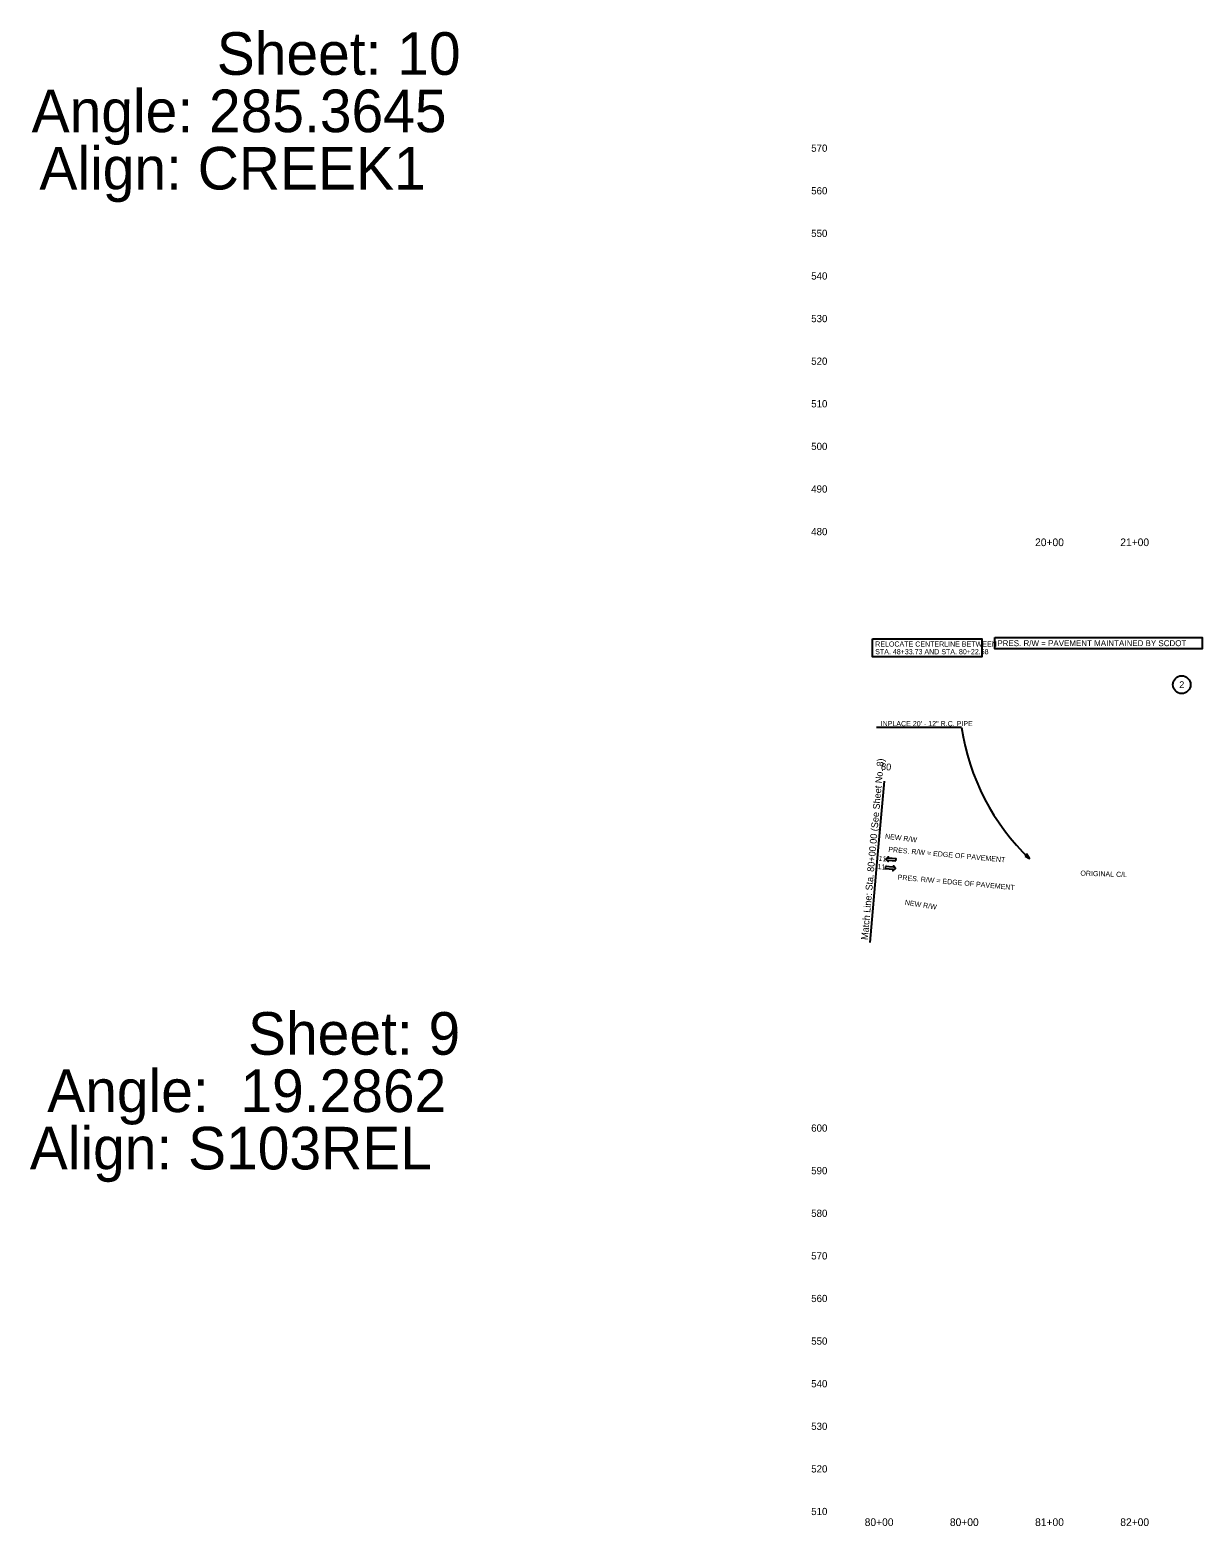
# Model space of a CAD drawing. Extents: x 1964377 to 1966966, y 1116414 to 1123213.
# Drawn here: x 1964377 to 1965753, y 1119864 to 1121620 of the extents above; entities that cross this region are included whole.
import ezdxf

# ---------------------------------------------------------------- set-up
doc = ezdxf.new("R2010")
doc.units = 0
for name, color, linetype in [('RD_DDB_Profile_Elev', 7, 'Continuous'), ('RD_DDB_StaTX', 7, 'Continuous'), ('RD_EX_DV_TX_Prop', 7, 'Continuous'), ('RD_EX_RW_TX', 7, 'Continuous'), ('RD_HC_Data_Rel', 7, 'Continuous'), ('RD_HC_TX_Rel_Sta50', 7, 'Continuous'), ('RD_PD_Final_LnLine', 7, 'Continuous'), ('RD_PD_Final_TX', 7, 'Continuous'), ('RD_PD_RW_TX', 7, 'Continuous'), ('RD_SHT_MatchLine', 7, 'Continuous'), ('RD_SHT_TX', 7, 'Continuous'), ('RD_TX_Drainage', 7, 'Continuous'), ('RD_TX_RoadID', 7, 'Continuous')]:
    doc.layers.add(name, color=color, linetype=linetype)

msp = doc.modelspace()

# ---------------------------------------------------------------- linework, layer by layer
at = {"layer": 'RD_EX_DV_TX_Prop'}
msp.add_circle((1965728.7, 1120851.4), 10.4, dxfattribs=at)
at = {"layer": 'RD_EX_RW_TX'}
msp.add_lwpolyline([(1965509.3, 1120906.6), (1965752.6, 1120906.6), (1965752.6, 1120893.6), (1965509.3, 1120893.6)], close=True, dxfattribs=at)
at = {"layer": 'RD_HC_Data_Rel'}
msp.add_lwpolyline([(1965365.9, 1120905.1), (1965494.2, 1120905.1), (1965494.2, 1120884.1), (1965365.9, 1120884.1)], close=True, dxfattribs=at)
at = {"layer": 'RD_PD_Final_LnLine'}
for points in [[(1965393.3, 1120644.5), (1965393.5, 1120646.9), (1965384.3, 1120647.7), (1965384.5, 1120649.3), (1965381.4, 1120646.8), (1965384, 1120643.7), (1965384.1, 1120645.3)], [(1965381, 1120638), (1965380.7, 1120635.6), (1965389.9, 1120634.8), (1965389.7, 1120633.1), (1965392.8, 1120635.7), (1965390.2, 1120638.8), (1965390.1, 1120637.1)]]:
    msp.add_lwpolyline(points, close=True, dxfattribs=at)
at = {"layer": 'RD_SHT_MatchLine'}
msp.add_lwpolyline([(1965362.9, 1120548.9), (1965371.4, 1120643.5), (1965380, 1120738.2)], dxfattribs=at)
at = {"layer": 'RD_TX_Drainage'}
msp.add_line((1965470.3, 1120801.2), (1965370.3, 1120801.2), dxfattribs=at)
msp.add_lwpolyline([(1965544.8, 1120650), (1965550.1, 1120647.2), (1965547, 1120652.3)], close=True, dxfattribs=at)
msp.add_arc((1965734.6, 1120840.4), 267.2, 188.445, 226.3357, dxfattribs=at)

# ---------------------------------------------------------------- texts
at = {"layer": 'RD_DDB_Profile_Elev'}
for s, p in [('570', (1965293.8, 1121476.8)), ('560', (1965293.8, 1121426.8)), ('550', (1965293.8, 1121376.8)), ('540', (1965293.8, 1121326.8)), ('530', (1965293.8, 1121276.8)), ('520', (1965293.8, 1121226.8)), ('510', (1965293.8, 1121176.8)), ('500', (1965293.8, 1121126.8)), ('490', (1965293.8, 1121076.8)), ('480', (1965293.8, 1121026.8)), ('600', (1965293.8, 1120326.8)), ('590', (1965293.8, 1120276.8)), ('580', (1965293.8, 1120226.8)), ('570', (1965293.8, 1120176.8)), ('560', (1965293.8, 1120126.8)), ('550', (1965293.8, 1120076.8)), ('540', (1965293.8, 1120026.8)), ('530', (1965293.8, 1119976.8)), ('520', (1965293.8, 1119926.8)), ('510', (1965293.8, 1119876.8))]:
    msp.add_text(s, height=8.5, dxfattribs=at).set_placement(p)
at = {"layer": 'RD_DDB_StaTX'}
for s, p in [('20+00', (1965556.6, 1121014)), ('21+00', (1965656.6, 1121014)), ('80+00', (1965356.6, 1119864)), ('80+00', (1965456.6, 1119864)), ('81+00', (1965556.6, 1119864)), ('82+00', (1965656.6, 1119864))]:
    msp.add_text(s, height=9, dxfattribs=at).set_placement(p)
at = {"layer": 'RD_EX_DV_TX_Prop'}
msp.add_text('2', height=8, dxfattribs=at).set_placement((1965725.8, 1120847.4))
at = {"layer": 'RD_EX_RW_TX'}
msp.add_text('PRES. R/W = PAVEMENT MAINTAINED BY SCDOT', height=7, dxfattribs=at).set_placement((1965512.3, 1120896.6))
for p in [(1965384.1, 1120655.2), (1965395.1, 1120622.6)]:
    msp.add_text('PRES. R/W = EDGE OF PAVEMENT', height=6, rotation=354.8631, dxfattribs=at).set_placement(p)
at = {"layer": 'RD_HC_Data_Rel'}
for s, p in [('STA. 48+33.73 AND STA. 80+22.58', (1965368.9, 1120887.1)), ('RELOCATE CENTERLINE BETWEEN', (1965368.9, 1120896.1))]:
    msp.add_text(s, height=6, dxfattribs=at).set_placement(p)
at = {"layer": 'RD_HC_TX_Rel_Sta50'}
msp.add_text('80', height=8, rotation=354.8631, dxfattribs=at).set_placement((1965375.5, 1120751.6))
at = {"layer": 'RD_PD_Final_TX'}
for p in [(1965372.8, 1120644.7), (1965371.3, 1120635.1)]:
    msp.add_text("11'", height=6, rotation=354.8631, dxfattribs=at).set_placement(p)
at = {"layer": 'RD_PD_RW_TX'}
for rotation, p in [(353.1957, (1965380.2, 1120670.7)), (351.2383, (1965403.4, 1120593.1))]:
    msp.add_text('NEW R/W', height=6, rotation=rotation, dxfattribs=at).set_placement(p)
at = {"layer": 'RD_SHT_MatchLine'}
msp.add_text('Match Line: Sta. 80+00.00 (See Sheet No. 8)', height=8, rotation=84.8631, dxfattribs=at).set_placement((1965360.2, 1120551.5))
at = {"layer": 'RD_SHT_TX'}
for s, p in [('Sheet: 10', (1964596, 1121567.1)), ('Angle: 285.3645', (1964378.7, 1121499.8)), ('Align: CREEK1', (1964387.8, 1121432.5)), ('Sheet: 9', (1964632.7, 1120417.1)), ('Angle:  19.2862', (1964397, 1120349.8)), ('Align: S103REL', (1964376.5, 1120282.5))]:
    msp.add_text(s, height=50, dxfattribs=at).set_placement(p)
at = {"layer": 'RD_TX_Drainage'}
msp.add_text('INPLACE 20\' - 12" R.C. PIPE', height=6, dxfattribs=at).set_placement((1965375.3, 1120802.7))
at = {"layer": 'RD_TX_RoadID'}
msp.add_text('ORIGINAL C/L', height=6, rotation=358.0875, dxfattribs=at).set_placement((1965609.7, 1120627.3))

doc.saveas('drawing.dxf')
